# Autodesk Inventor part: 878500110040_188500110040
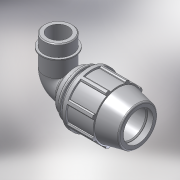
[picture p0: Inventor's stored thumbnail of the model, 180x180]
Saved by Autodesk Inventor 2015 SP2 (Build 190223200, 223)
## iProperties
Created: 2017-02
Part Number: 878500110040_188500110040
Material: PVC-Piping
Description: PLASSON 90° ELBOW MALE ADAPTOR 110-4"
Document SubType Name: Modeling
Designer: KIM
Mass: 92.6774 g
Surface Area: 199.44 cm^2
Volume: 66.1981 cm^3
Density: 1.4 g/cm^3
Appearance: Smooth - White
Author: KIM
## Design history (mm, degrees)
derived "87850.ipt"
feature "Solid1::87850.ipt"
tag "TaggingFeature1"
body "Solid1"
other parameters: "d4" = 23, "d5" = 69, "d7" = 181, "d9" = 39.42857, "d11" = 9.2, "d13" = 120 deg, "d14" = 132, "d15" = 12 deg, "d16" = 157.47, "d18" = 5.5, "d19" = 35 deg, "d20" = 17.5 deg, "d21" = 168.33, "d23" = 0, "d25" = 360 deg, "d27" = 3.62, "d33" = 2.2, "d42" = 102.12, "d43" = 5.43, "d46" = 3.3, "d51" = 276, "d68" = 18.4, "d73" = 113.03, "d74" = 42, "d75" = 129.9845, "d76" = 79.121, "d77" = 46.2, "d79" = 45.212, "d80" = 3.3909, "d83" = 0, "d84" = 0, "d91" = 135.75, "d93" = 196, "d94" = 113.03, "d95" = 79.121, "d96" = 18.4, "d97" = 50 deg, "d98" = 4.6, "d99" = 152.7459, "d100" = 4.6, "d101" = 4.6, "d102" = 12.06667, "d103" = 0, "E_" = 181, "A_" = 276, "l_" = 196, "l_2" = 42, "G_" = 113.03
